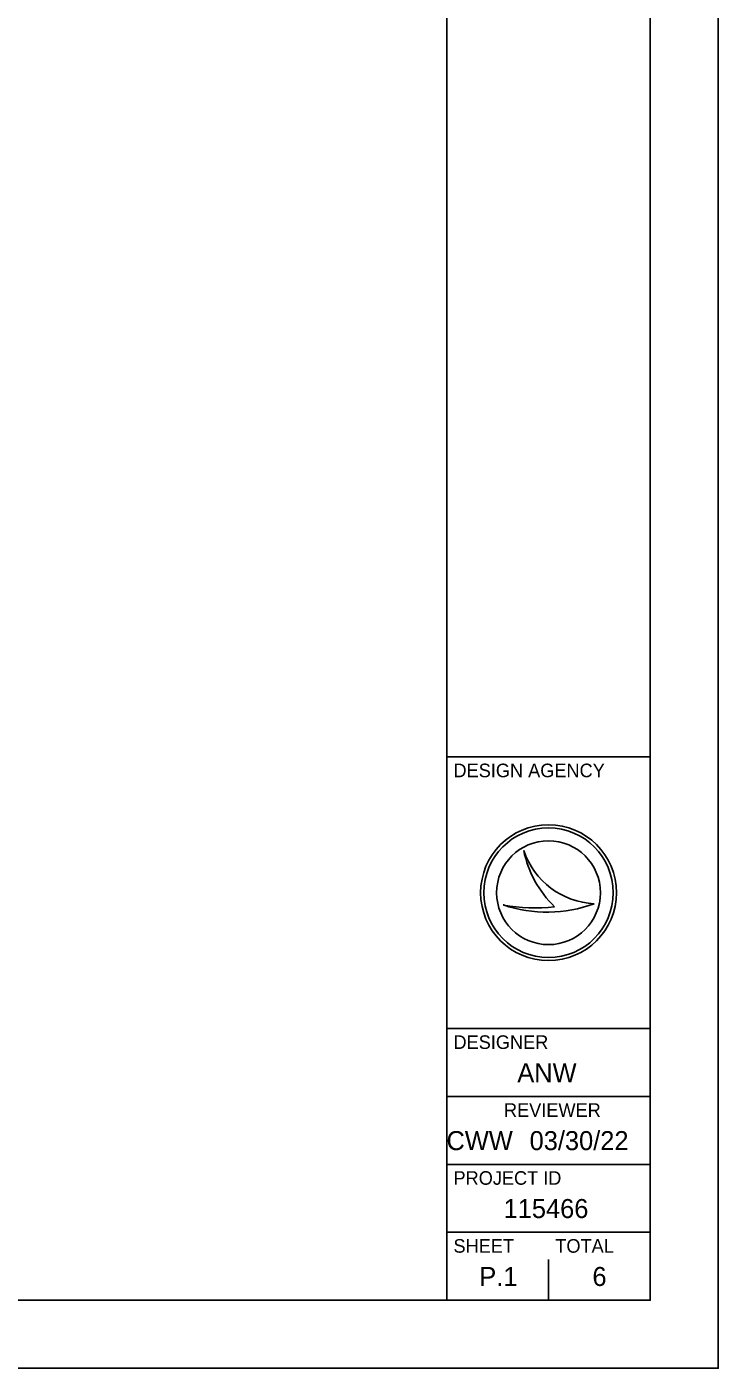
# Model space of a CAD drawing. Extents: x 0 to 68.9, y -26.1 to 22.
# Drawn here: x 28.91 to 34, y 0 to 9.87 of the extents above; entities that cross this region are included whole.
import ezdxf

# ---------------------------------------------------------------- set-up
doc = ezdxf.new("R2010")
doc.units = 0
for name, color, linetype in [('SH_Border', 7, 'Continuous'), ('SH_Cut_Line', 7, 'Continuous'), ('SH_Data', 7, 'Continuous')]:
    doc.layers.add(name, color=color, linetype=linetype)

msp = doc.modelspace()

# ---------------------------------------------------------------- linework, layer by layer
at = {"layer": 'SH_Border'}
for p, q in [((32, 0.5), (32, 21.5)), ((32, 4.5), (33.5, 4.5)), ((32, 2.5), (33.5, 2.5)), ((32, 2), (33.5, 2)), ((32, 1.5), (33.5, 1.5)), ((32, 1), (33.5, 1))]:
    msp.add_line(p, q, dxfattribs=at)
msp.add_lwpolyline([(1.5, 21.5), (33.5, 21.5), (33.5, 0.5), (1.5, 0.5)], close=True, dxfattribs=at)
at = {"layer": 'SH_Cut_Line'}
msp.add_lwpolyline([(0, 0), (34, 0), (34, 22), (0, 22)], close=True, dxfattribs=at)
at = {"layer": 'SH_Data'}
for p, q in [((32.5674, 3.8096), (32.5675, 3.8096)), ((32.75, 3.5), (32.75, 3.5)), ((32.4172, 3.4095), (32.4172, 3.4095)), ((33.0873, 3.4185), (33.0873, 3.4185)), ((32.75, 0.5), (32.75, 0.8)), ((32.375, 0.675), (32.375, 0.675))]:
    msp.add_line(p, q, dxfattribs=at)
for radius in [0.5, 0.4768, 0.4768, 0.3822]:
    msp.add_circle((32.75, 3.5), radius, dxfattribs=at)
for centre, radius, start, end in [((33.1159, 3.9976), 0.5798, 198.92567, 198.93195), ((33.3467, 3.9701), 0.7956, 191.63793, 191.64215), ((33.1159, 3.9976), 0.5798, 198.93195, 267.16574), ((33.3467, 3.9701), 0.7956, 191.64215, 226.09467), ((32.7394, 4.37), 1.0131, 251.45764, 290.08324), ((32.648, 4.6543), 1.2661, 259.49639, 259.49952), ((32.7394, 4.37), 1.0131, 251.45274, 251.45764), ((32.648, 4.6543), 1.2661, 259.49952, 276.66723)]:
    msp.add_arc(centre, radius, start, end, dxfattribs=at)

# ---------------------------------------------------------------- texts
for s, height, p in [('DESIGN AGENCY', 0.1, (32.05, 4.35)), ('DESIGNER', 0.1, (32.05, 2.35)), ('ANW', 0.14, (32.5202, 2.105)), ('REVIEWER', 0.1, (32.4218, 1.85)), ('CWW', 0.14, (31.9983, 1.605)), ('03/30/22', 0.14, (32.6107, 1.605)), ('PROJECT ID', 0.1, (32.05, 1.35)), ('115466', 0.14, (32.4191, 1.105)), ('SHEET', 0.1, (32.05, 0.85)), ('TOTAL', 0.1, (32.8, 0.85)), ('P.1', 0.14, (32.2403, 0.605)), ('6', 0.14, (33.0735, 0.605))]:
    msp.add_text(s, height=height, dxfattribs=at).set_placement(p)

doc.saveas('drawing.dxf')
